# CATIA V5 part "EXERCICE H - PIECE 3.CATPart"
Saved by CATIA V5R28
Part number: EXERCICE H - PIECE 3
Bounding box of the stored display mesh (mm): x 0 to 10, y -7 to 7, z -7 to 16
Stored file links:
  \\stisrv.epfl.ch\sti-sgm\sgm-ens\soubiell\Enseignement\ME-101-106 - Construction Mécanique I\1. Supports de cours\Z. Archives\2020\SW3\Modèles 3D exercice H\EXERCICE H - PIECE 3.CATPart
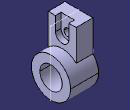
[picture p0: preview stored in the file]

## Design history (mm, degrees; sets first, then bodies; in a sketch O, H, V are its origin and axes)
Body1 (main body)
  Sketch1 on yz-plane, origin (0, 0, 0), H (0, 1, 0), V (0, 0, 1)
    circle A1 centre (0, 0) radius 7
    circle A2 centre (0, 0) radius 4
    radius A2 = 4
    radius A1 = 7
  Pad1: profile Sketch1, direction (1, 0, 0), length 10
  Sketch2 on start face of Pad1, origin (0, 0, 0), H (0, -1, 0), V (0, 0, 1)
    line L1 (-5, 4) -> (5, 4)
    line L2 (5, 4) -> (5, 16)
    line L3 (5, 16) -> (-5, 16)
    line L4 (-5, 16) -> (-5, 4)
    reference intersected line E1 through (0, 0) direction (0, -1) from zx-plane
    distance V L2 = 5
    distance L4 E1 = 5
    distance L1 H = 4
    distance L3 H = 16
    horizontal: L1 H, L3 H
    vertical: L2 V, L4 V
  Pad2: profile Sketch2, direction (1, 0, 0), length 6
  Sketch3 on end face of Pad2, origin (6, 0, 0), H (0, 1, 0), V (0, 0, 1)
    construction line L1 (0, 16) -> (0, 11)
    point P1 (0, 16)
    point P2 (0, 11)
    line L2 (2.4, 16) -> (2.4, 11)
    line L3 (-2.4, 11) -> (-2.4, 16)
    arc A1 centre (0, 11) radius 2.4 from (2.4, 11) to (-2.4, 11) cw
    arc A2 centre (0, 16) radius 2.4 from (-2.4, 16) to (2.4, 16) cw
    reference projected line E1 (-5, 16) -> (5, 16) from edge [end face of Pad2 | face of Pad2 from Sketch2.L3]
    reference projected line E2 (-5, 16) -> (5, 16) from edge [end face of Pad2 | face of Pad2 from Sketch2.L3]
    distance L1 L2 = 2.4
    distance E1 P2 = 5
    vertical: L1 V
    tangency: A1 L2, A2 L2, A1 L3, A2 L3
    coincidence: L1 V, P1 E2
  Pocket1: profile Sketch3, direction (-1, 0, 0), length 2
  Sketch4 on end face of Pocket1, origin (4, 0.6284, 10.4348), H (0, 1, 0), V (0, 0, 1)
    point P1 (-0.6284, 0.5652)
    reference projected arc E1 centre (-0.6284, 0.5652) radius 2.4 from (-3.0284, 0.5652) to (1.7716, 0.5652) ccw from edge [end face of Pocket1 | face of Pocket1 from Sketch3.A1]
    concentricity: E1 P1
  Hole1: placed by Sketch4, at (4, 0, 11) direction (-1, 0, 0), diameter 2.7, depth 10, V-bottom angle 120
  Sketch5 "PLAN DE COUPE C-C" on zx-plane, origin (0, 0, 0), H (-1, 0, 0), V (0, 0, 1)
    line L1 (0, 16) -> (-10, 16)
    line L2 (-10, 16) -> (-10, -7)
    line L3 (-10, -7) -> (0, -7)
    line L4 (0, -7) -> (0, 16)
    horizontal: L1 H, L3 H
    vertical: L2 V, L4 V
  Pocket2 "COUPE C-C": profile Sketch5, direction (0, -1, 0), through (limit type 6)
Current feature: Hole1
